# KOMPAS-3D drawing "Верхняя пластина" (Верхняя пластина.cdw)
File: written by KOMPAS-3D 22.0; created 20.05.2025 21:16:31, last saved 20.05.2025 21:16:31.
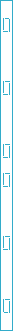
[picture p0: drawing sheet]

Sheet 1: A4, portrait

Document properties: Автор: user; Масса: 41.469866; Полное имя файла: Верхняя пластина.m3d

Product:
- Part/product: Верхняя пластина
    Масса: 41.469866

Title block, sheet 1: Наименование: Верхняя пластина; Материал: Сталь 10 ГОСТ 1050-2013; Масса: 41,47; Количество листов документа: 1; Форматы листов документа: A4

Views: Вид 1, Сверху
Referenced files in D:\Работа\2025\5. Май\Задание №6 - Тележка для крыши\3Д\Тележка в сборе\Корпус тележки\: Верхняя пластина.m3d
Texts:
  Без оформления
Dimensions and other numbers on the sheet: 8; 1:1; 1; 41,47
